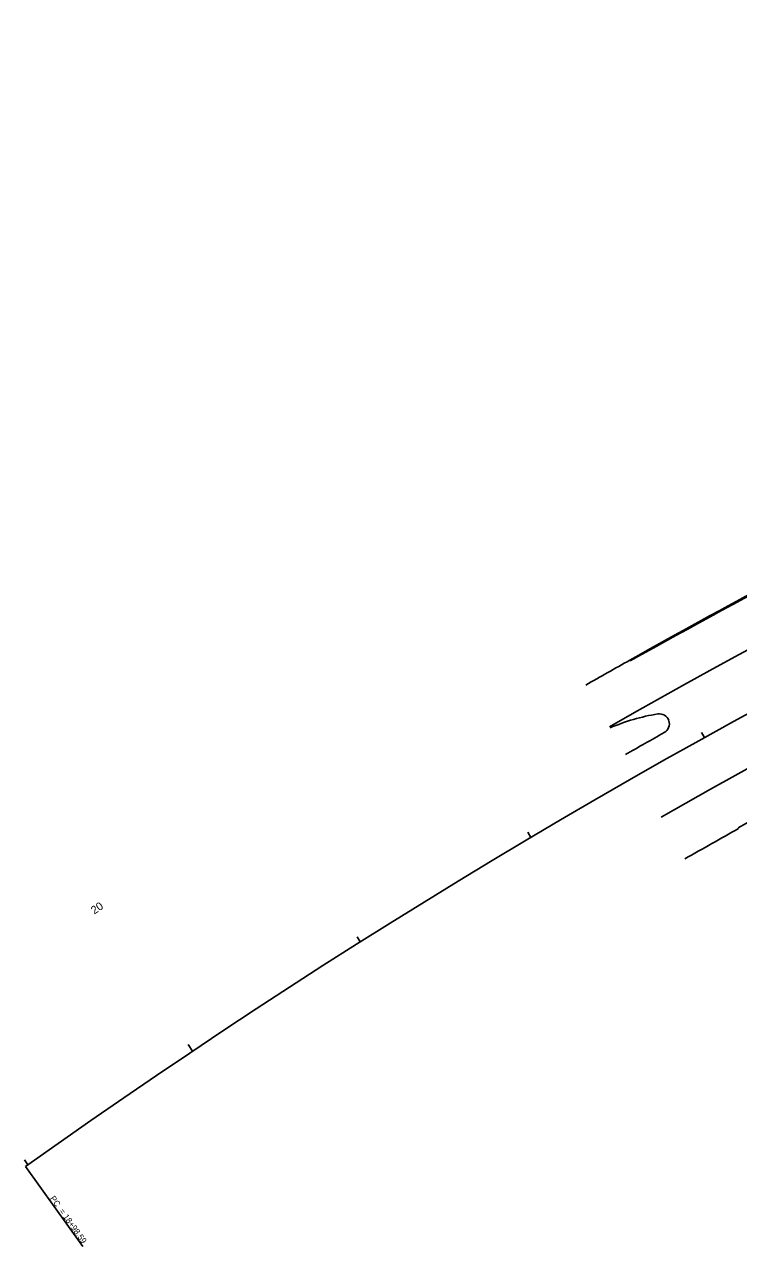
# Model space of a CAD drawing. Extents: x 2004390 to 2007638, y 1136392 to 1138193.
# Drawn here: x 2004390 to 2004747, y 1136392 to 1137003 of the extents above; entities that cross this region are included whole.
import ezdxf

# ---------------------------------------------------------------- set-up
doc = ezdxf.new("R2010")
doc.units = 0
for name, color, linetype in [('RD_HC_Cl', 7, 'Continuous'), ('RD_HC_Data', 7, 'Continuous'), ('RD_HC_Data_Tic', 7, 'Continuous'), ('RD_HC_TX_Sta20', 7, 'Continuous'), ('RD_PD_ConcMed', 7, 'Continuous'), ('RD_PD_Final_TrvlWay', 7, 'Continuous'), ('RD_PD_SideStreet', 7, 'Continuous')]:
    doc.layers.add(name, color=color, linetype=linetype)

msp = doc.modelspace()

# ---------------------------------------------------------------- linework, layer by layer
at = {"layer": 'RD_HC_Cl'}
msp.add_arc((2006499.76, 1133470.27), 3636, 105.38893, 125.45202, dxfattribs=at)
at = {"layer": 'RD_HC_Data'}
msp.add_line((2004390.8, 1136432.16), (2004419.31, 1136392.13), dxfattribs=at)
at = {"layer": 'RD_HC_Data_Tic'}
for p, q in [((2004729.97, 1136646.49), (2004728.5, 1136649.11)), ((2004643.29, 1136596.62), (2004641.76, 1136599.2)), ((2004558.02, 1136544.38), (2004556.42, 1136546.92)), ((2004474.22, 1136489.82), (2004471.99, 1136493.15)), ((2004391.95, 1136432.98), (2004390.21, 1136435.43))]:
    msp.add_line(p, q, dxfattribs=at)
at = {"layer": 'RD_PD_ConcMed'}
for centre, radius, start, end in [((2004722.61, 1136559.59), 100, 99.1723, 113.4276), ((2004707.47, 1136653.37), 5, 18.91828, 99.1723), ((2004707.47, 1136653.37), 5, 299.3823, 16.84962), ((2006499.76, 1133470.27), 3648, 119.3823, 119.73334)]:
    msp.add_arc(centre, radius, start, end, dxfattribs=at)
at = {"layer": 'RD_PD_Final_TrvlWay'}
for radius, start, end in [(3664, 105.38893, 119.73334), (3612, 105.38893, 119.73334), (3688, 116.80595, 119.33961), (3688, 119.33961, 119.73334), (3588, 119.24177, 119.73334)]:
    msp.add_arc((2006499.76, 1133470.27), radius, start, end, dxfattribs=at)
at = {"layer": 'RD_PD_SideStreet'}
for radius, start, end in [(3687.5, 116.10396, 119.33961), (3588.5, 116.79982, 119.24177)]:
    msp.add_arc((2006499.76, 1133470.27), radius, start, end, dxfattribs=at)

# ---------------------------------------------------------------- texts
at = {"layer": 'RD_HC_Data'}
msp.add_text('PC  = 18+98.59', height=3, rotation=305.45202, dxfattribs=at).set_placement((2004402.81, 1136416.16))
at = {"layer": 'RD_HC_TX_Sta20'}
msp.add_text('20', height=4, rotation=33.85404, dxfattribs=at).set_placement((2004425.09, 1136558.02))

doc.saveas('drawing.dxf')
